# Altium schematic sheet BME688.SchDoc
size A4; Revision: V1.2; SheetNumber: 9; SheetTotal: 10
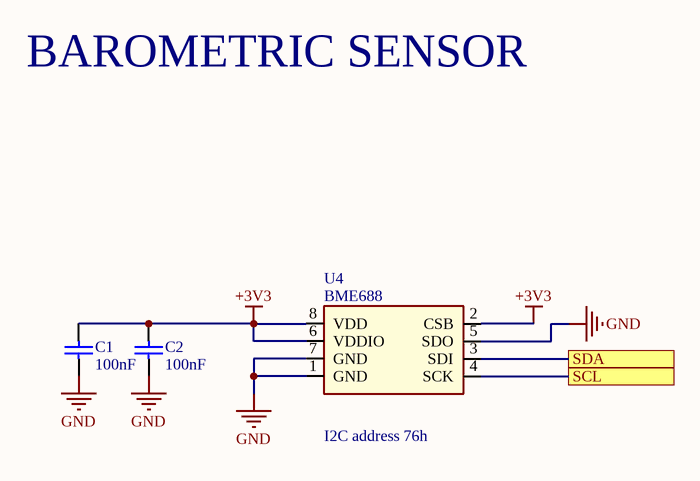
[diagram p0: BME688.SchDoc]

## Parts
C1  value 100nF  [CAP-0402]  (hidden comment: GRM155R61H104KE19D)
C2  value 100nF  [CAP-0402]  (hidden comment: GRM155R61H104KE19D)
U4  BME688  [BME680-Footprint-1]

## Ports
SCL, SDA

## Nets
+3V3: C1.2 C2.2 U4.2(CSB) U4.6(VDDIO) U4.8(VDD)
GND: C1.1 C2.1 U4.1(GND) U4.5(SDO) U4.7(GND)
SCL: U4.4(SCK) ; port SCL
SDA: U4.3(SDI) ; port SDA

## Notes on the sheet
- BAROMETRIC SENSOR
- (near U4) I2C address 76h

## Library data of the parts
C1 C2 = C0015-A.11: CAP CHIP 0402 100nF 50V X5R 10%; Manufacturer: Murata; Code Arduino: A5141
U4 = U0183-A.3: SENSOR PRESSURE TEMPERATURE HUMIDITY; Manufacturer: Bosch Sensortec; Code Arduino: U0183; Output Type: SPI,I2C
